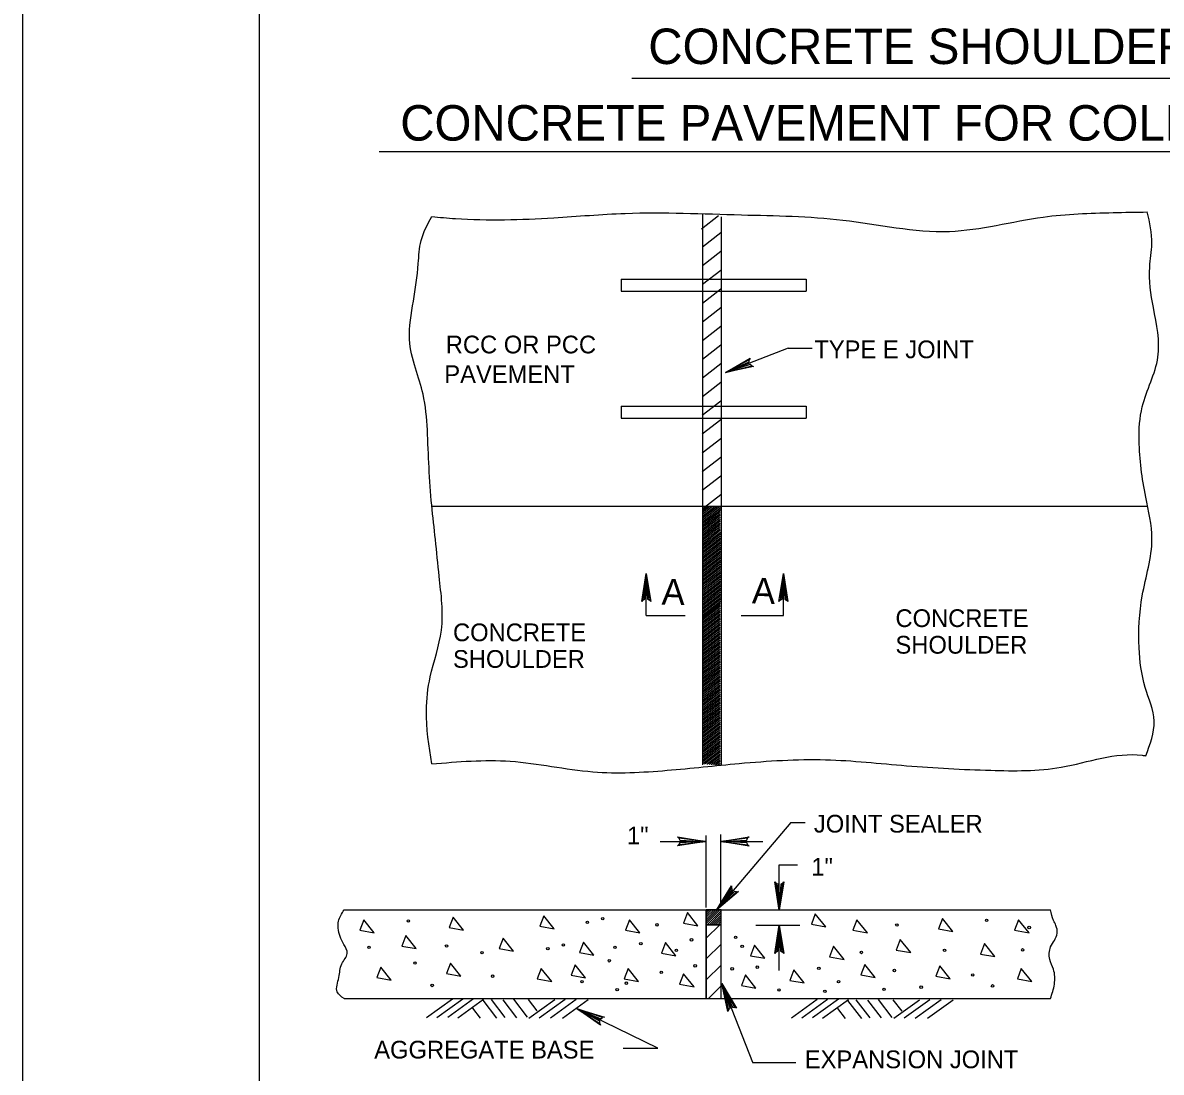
# Model space of a CAD drawing. Extents: x 638216 to 639962, y 297510 to 299292.
# Drawn here: x 638215.9 to 638408.4, y 297758.8 to 297936.3 of the extents above; entities that cross this region are included whole.
import ezdxf

# ---------------------------------------------------------------- set-up
doc = ezdxf.new("R2010")
doc.units = 0
for name, color, linetype in [('1', 7, 'Continuous'), ('2', 7, 'Continuous'), ('3', 7, 'Continuous'), ('PLT-BNDY', 7, 'Continuous')]:
    doc.layers.add(name, color=color, linetype=linetype)

msp = doc.modelspace()

# ---------------------------------------------------------------- linework, layer by layer
at = {"layer": '1'}
msp.add_lwpolyline([(639041.88, 297525.24), (639041.88, 298089.24), (638255.88, 298089.24), (638255.88, 297525.24), (639041.88, 297525.24), (639041.88, 297551.6), (638841.88, 297551.6), (638841.88, 297616.28), (639041.88, 297616.28), (639041.88, 297645.24), (638841.88, 297645.24), (638841.88, 297525.24), (638920.69, 297525.24), (638920.69, 297551.6), (638920.69, 297525.24), (638997.69, 297525.24), (638997.69, 297551.6), (638997.69, 297539.28), (639041.88, 297539.28)], dxfattribs=at)
msp.add_lwpolyline([(639041.88, 297525.24), (639041.88, 298089.24), (638255.88, 298089.24), (638255.88, 297525.24), (639041.88, 297525.24), (639041.88, 297551.6), (638841.88, 297551.6), (638841.88, 297616.28), (639041.88, 297616.28), (639041.88, 297645.24), (638841.88, 297645.24), (638841.88, 297525.24), (638920.69, 297525.24), (638920.69, 297551.6), (638920.69, 297525.24), (638997.69, 297525.24), (638997.69, 297551.6), (638997.69, 297539.28), (639041.88, 297539.28)], dxfattribs=at)
msp.add_lwpolyline([(639041.88, 297525.24), (639041.88, 298089.24), (638255.88, 298089.24), (638255.88, 297525.24), (639041.88, 297525.24), (639041.88, 297551.6), (638841.88, 297551.6), (638841.88, 297616.28), (639041.88, 297616.28), (639041.88, 297645.24), (638841.88, 297645.24), (638841.88, 297525.24), (638920.69, 297525.24), (638920.69, 297551.6), (638920.69, 297525.24), (638997.69, 297525.24), (638997.69, 297551.6), (638997.69, 297539.28), (639041.88, 297539.28)], dxfattribs=at)
at = {"layer": '2'}
for p, q in [((638318.87, 297926.94), (638537.44, 297926.94)), ((638276.14, 297914.52), (638568.21, 297914.52)), ((638330.83, 297904.06), (638330.83, 297810.8)), ((638333.95, 297903.47), (638333.95, 297810.8)), ((638317.07, 297892.92), (638348.32, 297892.92)), ((638317.07, 297892.92), (638317.07, 297890.92)), ((638348.32, 297892.92), (638348.32, 297890.92)), ((638317.07, 297890.92), (638348.32, 297890.92)), ((638345.29, 297881.3), (638334.71, 297877.15)), ((638345.29, 297881.3), (638349.34, 297881.3)), ((638317.07, 297871.45), (638348.32, 297871.45)), ((638317.07, 297871.45), (638317.07, 297869.45)), ((638348.32, 297871.45), (638348.32, 297869.45)), ((638317.07, 297869.45), (638348.32, 297869.45)), ((638285.03, 297854.53), (638405.95, 297854.53)), ((638321.31, 297836.07), (638321.31, 297843.19)), ((638344.5, 297836.07), (638344.5, 297843.19)), ((638321.31, 297836.07), (638327.86, 297836.07)), ((638337.38, 297836.07), (638344.5, 297836.07)), ((638345.77, 297801.05), (638333.2, 297786.23)), ((638345.77, 297801.05), (638348.2, 297801.05)), ((638333.92, 297786.8), (638333.92, 297799)), ((638323.65, 297797.85), (638331.37, 297797.85)), ((638331.42, 297786.67), (638331.42, 297798.85)), ((638333.92, 297797.85), (638341, 297797.85)), ((638343.8, 297786.27), (638343.8, 297793.91)), ((638343.8, 297793.91), (638346.86, 297793.91)), ((638270.21, 297786.27), (638389.65, 297786.27)), ((638331.46, 297771.27), (638331.46, 297786.27)), ((638331.46, 297786.27), (638333.96, 297786.27)), ((638333.96, 297771.27), (638333.96, 297786.27)), ((638331.46, 297783.77), (638333.96, 297783.77)), ((638339.83, 297783.67), (638347.27, 297783.67)), ((638343.8, 297776), (638343.8, 297783.67)), ((638339.3, 297760.44), (638334.11, 297773.81)), ((638270.21, 297771.27), (638389.65, 297771.27)), ((638288.52, 297771.15), (638284.16, 297768)), ((638290.27, 297771.15), (638285.9, 297768)), ((638292.11, 297771.24), (638287.75, 297768.09)), ((638293.79, 297771.11), (638289.43, 297767.96)), ((638293.67, 297770.98), (638296, 297767.96)), ((638295.07, 297771.11), (638297.4, 297768.09)), ((638297.03, 297771.07), (638299.36, 297768.04)), ((638298.83, 297771.15), (638301.16, 297768.13)), ((638301.33, 297771.11), (638302.81, 297769.19)), ((638305.82, 297771.07), (638301.46, 297767.92)), ((638307.57, 297771.13), (638303.2, 297767.98)), ((638309.46, 297771.11), (638305.09, 297767.96)), ((638311.51, 297771.07), (638307.15, 297767.92)), ((638350.21, 297771.11), (638345.84, 297767.96)), ((638351.95, 297771.11), (638347.59, 297767.96)), ((638353.8, 297771.19), (638349.43, 297768.04)), ((638355.48, 297771.07), (638351.11, 297767.92)), ((638355.35, 297770.94), (638357.68, 297767.92)), ((638356.76, 297771.07), (638359.09, 297768.04)), ((638358.71, 297771.03), (638361.04, 297768)), ((638360.52, 297771.11), (638362.85, 297768.09)), ((638363.02, 297771.07), (638364.5, 297769.15)), ((638367.51, 297771.03), (638363.14, 297767.88)), ((638369.25, 297771.09), (638364.89, 297767.94)), ((638371.14, 297771.07), (638366.77, 297767.92)), ((638373.2, 297771.03), (638368.83, 297767.88)), ((638291.95, 297769.64), (638293.25, 297767.95)), ((638323.29, 297762.88), (638309.63, 297769.56)), ((638353.63, 297769.6), (638354.93, 297767.91)), ((638317.38, 297762.88), (638323.29, 297762.88)), ((638339.29, 297760.45), (638346.6, 297760.45))]:
    msp.add_line(p, q, dxfattribs=at)
for points in [[(638330.65, 297901.46), (638333.52, 297903.69)], [(638330.83, 297898.41), (638333.93, 297900.82)], [(638330.82, 297895.24), (638333.93, 297897.65)], [(638330.82, 297892.08), (638333.93, 297894.49)], [(638330.81, 297888.91), (638333.93, 297891.33)], [(638330.81, 297885.75), (638333.93, 297888.16)], [(638330.8, 297882.58), (638333.92, 297885)], [(638330.8, 297879.42), (638333.92, 297881.84)], [(638330.79, 297876.25), (638333.92, 297878.67)], [(638339.14, 297878.28), (638338.87, 297878.52), (638334.71, 297877.15), (638339.14, 297878.28), (638339.43, 297878.18), (638334.71, 297877.15), (638338.7, 297878.95), (638338.72, 297879.31), (638334.71, 297877.15), (638338.87, 297879.6), (638338.72, 297879.31)], [(638330.79, 297873.09), (638333.92, 297875.51)], [(638330.78, 297869.92), (638333.92, 297872.35)], [(638330.78, 297866.76), (638333.91, 297869.19)], [(638330.77, 297863.59), (638333.91, 297866.02)], [(638330.77, 297860.43), (638333.91, 297862.86)], [(638330.77, 297857.26), (638333.91, 297859.7)], [(638330.91, 297854.22), (638333.91, 297856.53)], [(638330.79, 297854.14), (638330.82, 297854.16)], [(638330.8, 297852.25), (638333.75, 297854.53)], [(638330.8, 297852.56), (638333.34, 297854.53)], [(638330.8, 297852.88), (638332.93, 297854.53)], [(638330.8, 297853.19), (638332.53, 297854.53)], [(638330.8, 297853.51), (638332.12, 297854.53)], [(638330.8, 297853.83), (638331.71, 297854.53)], [(638330.8, 297851.93), (638333.95, 297854.37)], [(638330.8, 297851.62), (638333.95, 297854.06)], [(638330.8, 297851.3), (638333.82, 297853.64)], [(638330.81, 297850.99), (638333.82, 297853.32)], [(638330.81, 297850.67), (638333.82, 297853.01)], [(638330.81, 297850.36), (638333.82, 297852.69)], [(638330.81, 297850.04), (638333.82, 297852.38)], [(638330.81, 297849.73), (638333.82, 297852.06)], [(638330.81, 297849.41), (638333.82, 297851.74)], [(638330.81, 297849.1), (638333.82, 297851.43)], [(638330.82, 297848.78), (638333.82, 297851.11)], [(638330.82, 297848.47), (638333.82, 297850.8)], [(638330.82, 297848.15), (638333.82, 297850.48)], [(638330.82, 297847.84), (638333.83, 297850.16)], [(638330.82, 297847.52), (638333.83, 297849.85)], [(638330.82, 297847.21), (638333.83, 297849.53)], [(638330.82, 297846.89), (638333.83, 297849.22)], [(638330.82, 297846.58), (638333.83, 297848.9)], [(638330.82, 297846.26), (638333.83, 297848.59)], [(638330.83, 297845.94), (638333.83, 297848.27)], [(638330.83, 297845.63), (638333.83, 297847.95)], [(638330.83, 297845.31), (638333.83, 297847.64)], [(638330.83, 297845), (638333.83, 297847.32)], [(638330.83, 297844.68), (638333.83, 297847.01)], [(638330.83, 297844.37), (638333.83, 297846.69)], [(638330.83, 297844.05), (638333.83, 297846.38)], [(638330.83, 297843.74), (638333.83, 297846.06)], [(638330.83, 297843.42), (638333.83, 297845.74)], [(638330.84, 297843.11), (638333.83, 297845.43)], [(638330.84, 297842.79), (638333.83, 297845.11)], [(638320.74, 297838.65), (638321.07, 297838.82), (638321.31, 297843.19), (638320.74, 297838.65), (638320.54, 297838.41), (638321.31, 297843.19), (638321.53, 297838.82), (638321.85, 297838.66), (638321.31, 297843.19), (638322.07, 297838.41), (638321.85, 297838.66)], [(638330.84, 297842.48), (638333.83, 297844.8)], [(638330.84, 297842.16), (638333.83, 297844.48)], [(638330.84, 297841.85), (638333.84, 297844.17)], [(638330.84, 297841.53), (638333.84, 297843.85)], [(638330.84, 297841.22), (638333.84, 297843.53)], [(638330.84, 297840.9), (638333.84, 297843.22)], [(638343.93, 297838.65), (638344.26, 297838.81), (638344.5, 297843.19), (638343.93, 297838.65), (638343.73, 297838.41), (638344.5, 297843.19), (638344.72, 297838.82), (638345.04, 297838.66), (638344.5, 297843.19), (638345.26, 297838.41), (638345.04, 297838.66)], [(638330.84, 297840.59), (638333.84, 297842.9)], [(638330.85, 297840.27), (638333.84, 297842.59)], [(638330.85, 297839.96), (638333.84, 297842.27)], [(638330.85, 297839.64), (638333.84, 297841.95)], [(638330.85, 297839.32), (638333.84, 297841.64)], [(638330.85, 297839.01), (638333.84, 297841.32)], [(638330.85, 297838.69), (638333.84, 297841.01)], [(638330.85, 297838.38), (638333.84, 297840.69)], [(638330.85, 297838.06), (638333.84, 297840.38)], [(638330.86, 297837.75), (638333.84, 297840.06)], [(638330.86, 297837.43), (638333.84, 297839.74)], [(638330.86, 297837.12), (638333.84, 297839.43)], [(638330.79, 297835.63), (638333.78, 297837.94)], [(638330.79, 297835.32), (638333.78, 297837.63)], [(638330.83, 297835.92), (638333.81, 297838.23)], [(638330.86, 297836.8), (638333.84, 297839.11)], [(638330.86, 297836.49), (638333.84, 297838.8)], [(638330.86, 297836.17), (638333.85, 297838.48)], [(638330.8, 297835), (638333.78, 297837.31)], [(638330.8, 297834.69), (638333.78, 297836.99)], [(638330.8, 297834.37), (638333.78, 297836.68)], [(638330.8, 297834.06), (638333.78, 297836.36)], [(638330.8, 297833.74), (638333.78, 297836.05)], [(638330.8, 297833.43), (638333.78, 297835.73)], [(638330.8, 297833.11), (638333.78, 297835.42)], [(638330.8, 297832.79), (638333.78, 297835.1)], [(638330.81, 297832.48), (638333.78, 297834.78)], [(638330.81, 297832.16), (638333.78, 297834.47)], [(638330.81, 297831.85), (638333.78, 297834.15)], [(638330.81, 297831.53), (638333.78, 297833.84)], [(638330.81, 297831.22), (638333.78, 297833.52)], [(638330.81, 297830.9), (638333.78, 297833.2)], [(638330.81, 297830.59), (638333.78, 297832.89)], [(638330.81, 297830.27), (638333.78, 297832.57)], [(638330.82, 297829.96), (638333.79, 297832.26)], [(638330.82, 297829.64), (638333.79, 297831.94)], [(638330.82, 297829.33), (638333.79, 297831.63)], [(638330.82, 297829.01), (638333.79, 297831.31)], [(638330.82, 297828.7), (638333.79, 297830.99)], [(638330.82, 297828.38), (638333.79, 297830.68)], [(638330.82, 297828.07), (638333.79, 297830.36)], [(638330.82, 297827.75), (638333.79, 297830.05)], [(638330.82, 297827.44), (638333.79, 297829.73)], [(638330.83, 297827.12), (638333.79, 297829.42)], [(638330.83, 297826.8), (638333.79, 297829.1)], [(638330.83, 297826.49), (638333.79, 297828.78)], [(638330.83, 297826.17), (638333.79, 297828.47)], [(638330.83, 297825.86), (638333.79, 297828.15)], [(638330.83, 297825.54), (638333.79, 297827.84)], [(638330.83, 297825.23), (638333.79, 297827.52)], [(638330.83, 297824.91), (638333.79, 297827.2)], [(638330.83, 297824.6), (638333.79, 297826.89)], [(638330.84, 297824.28), (638333.8, 297826.57)], [(638330.84, 297823.97), (638333.79, 297826.26)], [(638330.84, 297823.65), (638333.8, 297825.94)], [(638330.84, 297823.34), (638333.8, 297825.63)], [(638330.84, 297823.02), (638333.8, 297825.31)], [(638330.84, 297822.71), (638333.8, 297824.99)], [(638330.84, 297822.39), (638333.8, 297824.68)], [(638330.85, 297822.08), (638333.8, 297824.36)], [(638330.85, 297821.76), (638333.8, 297824.05)], [(638330.85, 297821.45), (638333.8, 297823.73)], [(638330.85, 297821.13), (638333.8, 297823.42)], [(638330.85, 297820.82), (638333.8, 297823.1)], [(638330.85, 297820.5), (638333.8, 297822.78)], [(638330.85, 297820.19), (638333.8, 297822.47)], [(638330.85, 297819.87), (638333.8, 297822.15)], [(638330.85, 297819.55), (638333.8, 297821.84)], [(638330.86, 297819.24), (638333.8, 297821.52)], [(638330.86, 297818.92), (638333.8, 297821.21)], [(638330.86, 297818.61), (638333.8, 297820.89)], [(638330.86, 297818.29), (638333.8, 297820.57)], [(638330.86, 297817.98), (638333.81, 297820.26)], [(638330.86, 297817.66), (638333.81, 297819.94)], [(638330.86, 297817.35), (638333.81, 297819.63)], [(638330.86, 297817.03), (638333.81, 297819.31)], [(638330.86, 297816.72), (638333.81, 297818.99)], [(638330.87, 297816.4), (638333.81, 297818.68)], [(638330.87, 297816.09), (638333.81, 297818.36)], [(638330.87, 297815.77), (638333.81, 297818.05)], [(638330.87, 297815.46), (638333.81, 297817.73)], [(638330.87, 297815.14), (638333.81, 297817.42)], [(638330.87, 297814.83), (638333.81, 297817.1)], [(638330.87, 297814.51), (638333.81, 297816.79)], [(638330.87, 297814.2), (638333.81, 297816.47)], [(638330.87, 297813.88), (638333.81, 297816.15)], [(638330.88, 297813.57), (638333.81, 297815.84)], [(638330.88, 297813.25), (638333.81, 297815.52)], [(638330.88, 297812.93), (638333.81, 297815.21)], [(638330.88, 297812.62), (638333.81, 297814.89)], [(638330.88, 297812.3), (638333.82, 297814.58)], [(638330.88, 297811.99), (638333.81, 297814.26)], [(638330.88, 297811.67), (638333.81, 297813.94)], [(638330.89, 297811.36), (638333.82, 297813.63)], [(638330.89, 297811.04), (638333.82, 297813.31)], [(638331.18, 297810.95), (638333.82, 297813)], [(638331.55, 297810.93), (638333.82, 297812.68)], [(638331.92, 297810.9), (638333.82, 297812.36)], [(638332.29, 297810.87), (638333.82, 297812.05)], [(638332.66, 297810.84), (638333.82, 297811.73)], [(638333.04, 297810.81), (638333.82, 297811.42)], [(638333.41, 297810.78), (638333.82, 297811.1)], [(638333.78, 297810.75), (638333.82, 297810.79)], [(638326.82, 297798.42), (638326.99, 297798.09), (638331.37, 297797.85), (638326.82, 297798.42), (638326.59, 297798.62), (638331.37, 297797.85), (638327, 297797.64), (638326.84, 297797.31), (638331.37, 297797.85), (638326.59, 297797.09), (638326.84, 297797.31)], [(638338.46, 297797.28), (638338.3, 297797.61), (638333.92, 297797.85), (638338.46, 297797.28), (638338.7, 297797.08), (638333.92, 297797.85), (638338.29, 297798.07), (638338.45, 297798.39), (638333.92, 297797.85), (638338.7, 297798.61), (638338.45, 297798.39)], [(638336.57, 297789.33), (638336.21, 297789.41), (638333.2, 297786.23), (638336.57, 297789.33), (638336.88, 297789.38), (638333.2, 297786.23), (638335.86, 297789.7), (638335.72, 297790.04), (638333.2, 297786.23), (638335.71, 297790.36), (638335.72, 297790.04)], [(638344.37, 297790.78), (638344.04, 297790.61), (638343.8, 297786.23), (638344.37, 297790.78), (638344.57, 297791.01), (638343.8, 297786.23), (638343.59, 297790.6), (638343.26, 297790.76), (638343.8, 297786.23), (638343.04, 297791.01), (638343.26, 297790.76)], [(638331.46, 297783.97), (638333.77, 297786.27)], [(638331.46, 297784.32), (638333.41, 297786.27)], [(638331.46, 297784.67), (638333.06, 297786.27)], [(638331.46, 297785.03), (638332.71, 297786.27)], [(638331.46, 297785.38), (638332.35, 297786.27)], [(638331.46, 297785.74), (638332, 297786.27)], [(638331.46, 297786.09), (638331.64, 297786.27)], [(638331.62, 297783.77), (638333.96, 297786.11)], [(638331.97, 297783.77), (638333.96, 297785.76)], [(638332.33, 297783.77), (638333.96, 297785.41)], [(638331.46, 297781.52), (638333.72, 297783.77)], [(638332.68, 297783.77), (638333.96, 297785.05)], [(638333.03, 297783.77), (638333.96, 297784.7)], [(638333.39, 297783.77), (638333.96, 297784.35)], [(638333.74, 297783.77), (638333.96, 297783.99)], [(638343.23, 297779.14), (638343.56, 297779.3), (638343.8, 297783.67), (638343.23, 297779.14), (638343.03, 297778.9), (638343.8, 297783.67), (638344.02, 297779.31), (638344.34, 297779.15), (638343.8, 297783.67), (638344.56, 297778.9), (638344.34, 297779.15)], [(638331.46, 297777.98), (638333.96, 297780.48)], [(638331.46, 297774.45), (638333.96, 297776.95)], [(638331.82, 297771.27), (638333.96, 297773.41)], [(638335.22, 297769.37), (638335.47, 297769.64), (638334.11, 297773.81), (638335.22, 297769.37), (638335.12, 297769.08), (638334.11, 297773.81), (638335.9, 297769.81), (638336.26, 297769.78), (638334.11, 297773.81), (638336.55, 297769.63), (638336.26, 297769.78)], [(638313.46, 297767.06), (638313.45, 297767.43), (638309.63, 297769.56), (638313.46, 297767.06), (638313.58, 297766.78), (638309.63, 297769.56), (638313.65, 297767.84), (638313.93, 297768.06), (638309.63, 297769.56), (638314.25, 297768.15), (638313.93, 297768.06)]]:
    msp.add_lwpolyline(points, dxfattribs=at)
for points in [[(638328.27, 297785.81), (638327.6, 297784.02), (638330.03, 297783.58)], [(638331.46, 297786.27), (638331.46, 297783.77), (638333.96, 297783.77), (638333.96, 297786.27)], [(638349.89, 297785.62), (638349.22, 297783.84), (638351.65, 297783.39)], [(638273.53, 297784.61), (638272.86, 297782.83), (638275.3, 297782.39)], [(638288.65, 297785.05), (638287.98, 297783.27), (638290.41, 297782.83)], [(638304, 297785.28), (638303.32, 297783.5), (638305.76, 297783.06)], [(638318.46, 297784.61), (638317.79, 297782.83), (638320.23, 297782.39)], [(638331.46, 297783.77), (638331.46, 297771.27), (638333.96, 297771.27), (638333.96, 297783.77)], [(638356.93, 297784.61), (638356.26, 297782.83), (638358.69, 297782.39)], [(638371.37, 297784.84), (638370.7, 297783.06), (638373.14, 297782.61)], [(638384.26, 297784.61), (638383.59, 297782.83), (638386.03, 297782.39)], [(638280.65, 297781.94), (638279.98, 297780.16), (638282.41, 297779.72)], [(638297.11, 297781.5), (638296.44, 297779.72), (638298.87, 297779.28)], [(638310.67, 297780.83), (638310, 297779.05), (638312.44, 297778.61)], [(638324.55, 297780.75), (638323.88, 297778.96), (638326.32, 297778.52)], [(638339.58, 297780.31), (638338.91, 297778.53), (638341.35, 297778.09)], [(638352.97, 297780.14), (638352.3, 297778.36), (638354.74, 297777.91)], [(638364.25, 297781.27), (638363.58, 297779.49), (638366.02, 297779.05)], [(638378.49, 297780.6), (638377.82, 297778.81), (638380.25, 297778.38)], [(638276.43, 297776.61), (638275.76, 297774.83), (638278.19, 297774.39)], [(638288.21, 297777.28), (638287.54, 297775.5), (638289.97, 297775.06)], [(638303.56, 297776.38), (638302.88, 297774.6), (638305.32, 297774.15)], [(638309.28, 297777), (638308.61, 297775.21), (638311.05, 297774.77)], [(638318.23, 297776.38), (638317.56, 297774.6), (638320, 297774.15)], [(638346.23, 297776.15), (638345.56, 297774.36), (638348, 297773.92)], [(638358.25, 297777.05), (638357.58, 297775.27), (638360.01, 297774.83)], [(638370.93, 297776.82), (638370.26, 297775.04), (638372.7, 297774.6)], [(638384.72, 297776.38), (638384.05, 297774.6), (638386.49, 297774.15)], [(638327.62, 297775.48), (638326.95, 297773.69), (638329.38, 297773.25)], [(638338.07, 297775.29), (638337.4, 297773.5), (638339.84, 297773.06)]]:
    msp.add_lwpolyline(points, close=True, dxfattribs=at)
for centre in [(638281.09, 297784.4), (638311.35, 297784.17), (638313.94, 297784.79), (638323.12, 297783.75), (638363.68, 297783.71), (638378.85, 297784.5), (638386.05, 297783.29), (638336.41, 297781.63), (638274.44, 297779.95), (638287.54, 297780.16), (638304.67, 297779.72), (638307.29, 297780.34), (638316.01, 297779.95), (638320.39, 297780.55), (638326.39, 297779.43), (638328.96, 297781.21), (638337.52, 297780.1), (638371.74, 297779.43), (638384.94, 297779.51), (638293.54, 297779.05), (638315.06, 297777.67), (638357.67, 297779.08), (638282.2, 297777.28), (638323.84, 297775.71), (638329.57, 297776.82), (638335.83, 297776.3), (638340.07, 297776.59), (638350.48, 297776.38), (638363.25, 297776.03), (638295.33, 297775.06), (638310.44, 297774.15), (638317.95, 297773.89), (638353.82, 297774.15), (638376.5, 297775.27), (638285.1, 297773.5), (638316.38, 297772.79), (638343.74, 297772.73), (638351.51, 297772.5), (638361.51, 297772.83), (638367.78, 297773.21), (638379.86, 297773.42)]:
    msp.add_circle(centre, 0.21, dxfattribs=at)
for points in [[(638284.3, 297867.46), (638283.57, 297873.48), (638282.27, 297877.87), (638281.29, 297882.74), (638281.94, 297889.24), (638282.75, 297895.57), (638283.24, 297899.47), (638285.03, 297903.52)], [(638285.03, 297903.52), (638289.03, 297903.19), (638305.66, 297903.32), (638317.74, 297904.07), (638337.41, 297903.82), (638354.54, 297902.94), (638372.56, 297901.03), (638388.43, 297903.44), (638400.23, 297904.2), (638406.02, 297904.31)], [(638405.76, 297812.35), (638407.18, 297818.19), (638405.67, 297823.9), (638404.64, 297830.62), (638405.17, 297839.4), (638406.81, 297849.03), (638405.76, 297856.1), (638404.64, 297865.66), (638405.17, 297871.37), (638407.82, 297879.75), (638407.06, 297888.13), (638406.43, 297894.97), (638406.81, 297898.92), (638406.02, 297904.31)], [(638285.03, 297810.96), (638284.13, 297819.97), (638284.78, 297825.68), (638286.67, 297833.56), (638286.29, 297842.69), (638285.66, 297848.9), (638285.03, 297854.71), (638284.3, 297867.46)], [(638285.03, 297810.96), (638298.32, 297811.42), (638312.28, 297809.63), (638324.83, 297809.88), (638337.03, 297811.04), (638351.62, 297811.67), (638365.33, 297810.66), (638379.55, 297809.88), (638391.47, 297810.41), (638405.18, 297812.43), (638405.76, 297812.35)], [(638270.21, 297771.27), (638269.06, 297772.39), (638269.33, 297774.85), (638269.84, 297777.16), (638270.74, 297778.9), (638270.17, 297780.45), (638269.21, 297783.18), (638269.27, 297784.36), (638270.21, 297786.27)], [(638389.65, 297771.27), (638390.31, 297773.71), (638390.16, 297776.23), (638389.53, 297777.91), (638389.68, 297780.01), (638390.31, 297781.12), (638390.79, 297782.32), (638390.58, 297783.64), (638390.16, 297784.48), (638389.65, 297786.27)]]:
    msp.add_spline(points, degree=3, dxfattribs=at)
at = {"layer": 'PLT-BNDY'}
msp.add_lwpolyline([(638215.88, 298104.24), (639056.88, 298104.24), (639056.88, 297510.24), (638215.88, 297510.24)], close=True, dxfattribs=at)

# ---------------------------------------------------------------- texts
at = {"layer": '3'}
for s, height, p in [('CONCRETE SHOULDERS ADJACENT TO PLAIN ', 6, (638321.65, 297929.32)), ('CONCRETE PAVEMENT FOR COLLECTORS AND LOCAL ROADS', 6, (638279.71, 297916.37)), ('RCC OR PCC', 3, (638287.41, 297880.39)), ('TYPE E JOINT', 3, (638349.72, 297879.57)), ('PAVEMENT', 3, (638287.16, 297875.38)), ('CONCRETE', 3, (638363.44, 297834.11)), ('CONCRETE', 3, (638288.63, 297831.71)), ('SHOULDER', 3, (638363.44, 297829.61)), ('SHOULDER', 3, (638288.63, 297827.21)), ('JOINT SEALER', 3, (638349.65, 297799.35)), ('1"', 3, (638318.04, 297797.35)), ('1"', 3, (638349.21, 297792.06)), ('AGGREGATE BASE', 3, (638275.31, 297761.14)), ('EXPANSION JOINT', 3, (638348.11, 297759.5))]:
    msp.add_text(s, height=height, dxfattribs=at).set_placement(p)
for p in [(638323.88, 297837.92), (638339.14, 297838.1)]:
    msp.add_text('A', height=4.37, rotation=358.7448, dxfattribs=at).set_placement(p)

doc.saveas('drawing.dxf')
